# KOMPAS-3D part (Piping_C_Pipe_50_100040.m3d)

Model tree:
1. Plane XY
2. Plane ZX
3. Plane ZY
4. X Axis
5. Y Axis
6. Z Axis
7. Origin
8. Path  (labels: Труба Dy 50; Отвод 90 Dy 50)
9. Plane of section
10. Section of pipe
11. Pipe
     Толщина стенки 1 = 1

Referenced files in C:\Program Files\ASCON\KOMPAS-3D V10\Libs\Piping\Models\Tanks\: Tanks.a3d
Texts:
  Pipe Dn 50
  Three Point Plane
  Plane at Angle
  Line and Point Plane
  Axis through Two Vertices
  Axis of Feature
  Axis of Conical Surface
  Axis through Edge
  Приклеить элемент выдавливания
  Приклеить элемент вращения
  Приклеить кинематический элемент
  Приклеить элемент по сечениям
  Trim by Surface
  Trim by Sketch
  Feature with No History
  Intersection Axis of Two Planes
  Two Line Plane
  Line and Face Plane
  Bend by line
  Hole in sheet body
  Cut in sheet body
  Point in CM
  Linear Dimension from Line to Point
  Surface Finish Symbol
  Geometric Tolerance Symbol
  Текст на чертеже
  Линия-выноска #1
  Линия-выноска #2
  Линия-выноска #3
  Отклонения формы и база
  Марка координационной оси
  Марка/позиционное обозначение с линией-выноской
  Марка/позиционное обозначение на линии
  Марка/позиционное обозначение без линии-выноски
  Труба Dy 50
  Отвод 90 Dy 50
